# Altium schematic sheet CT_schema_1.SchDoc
size 446 x 435 mm
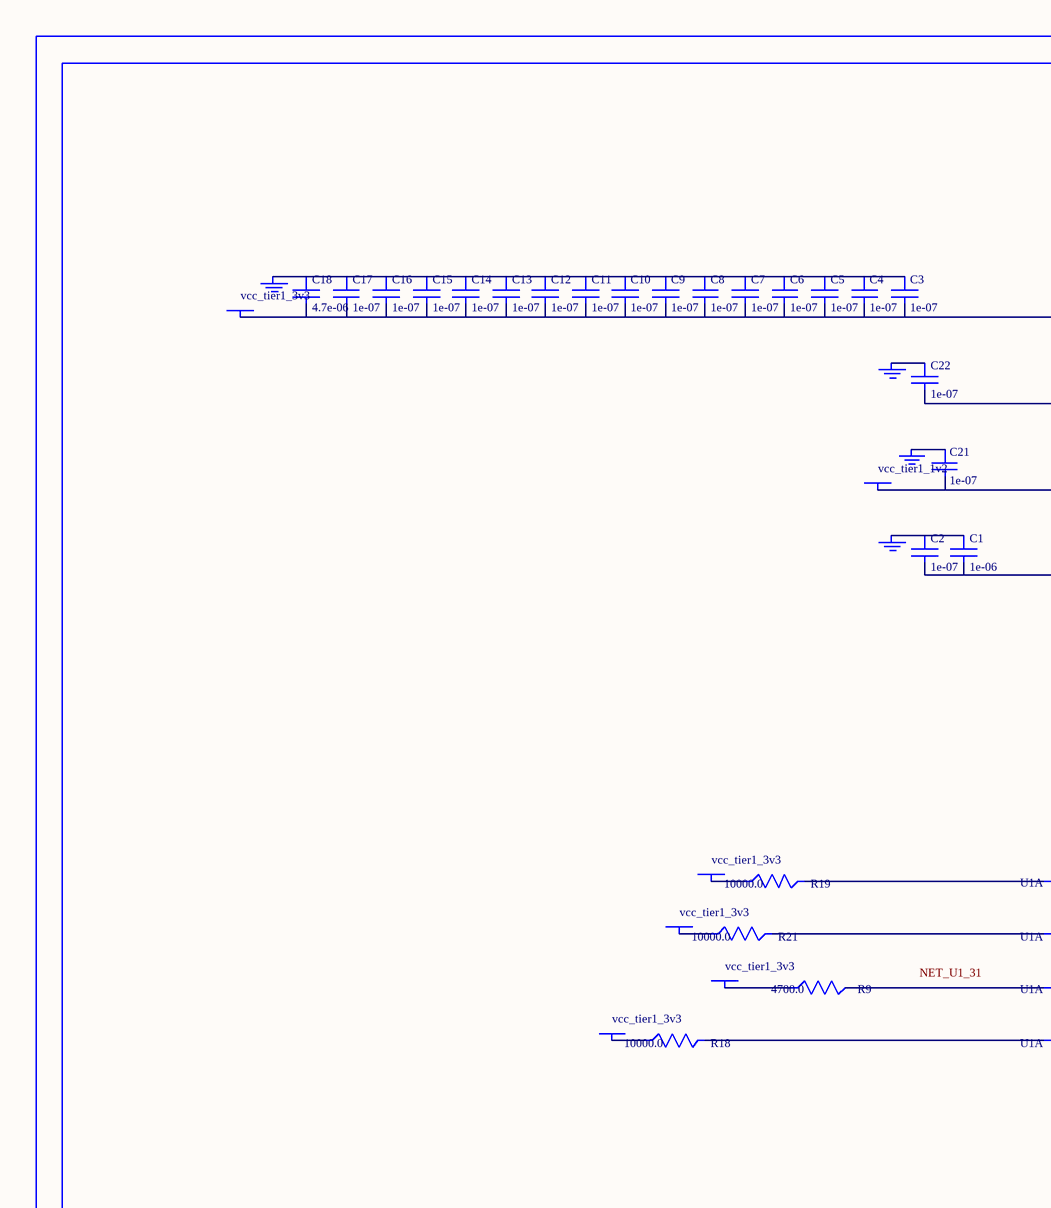
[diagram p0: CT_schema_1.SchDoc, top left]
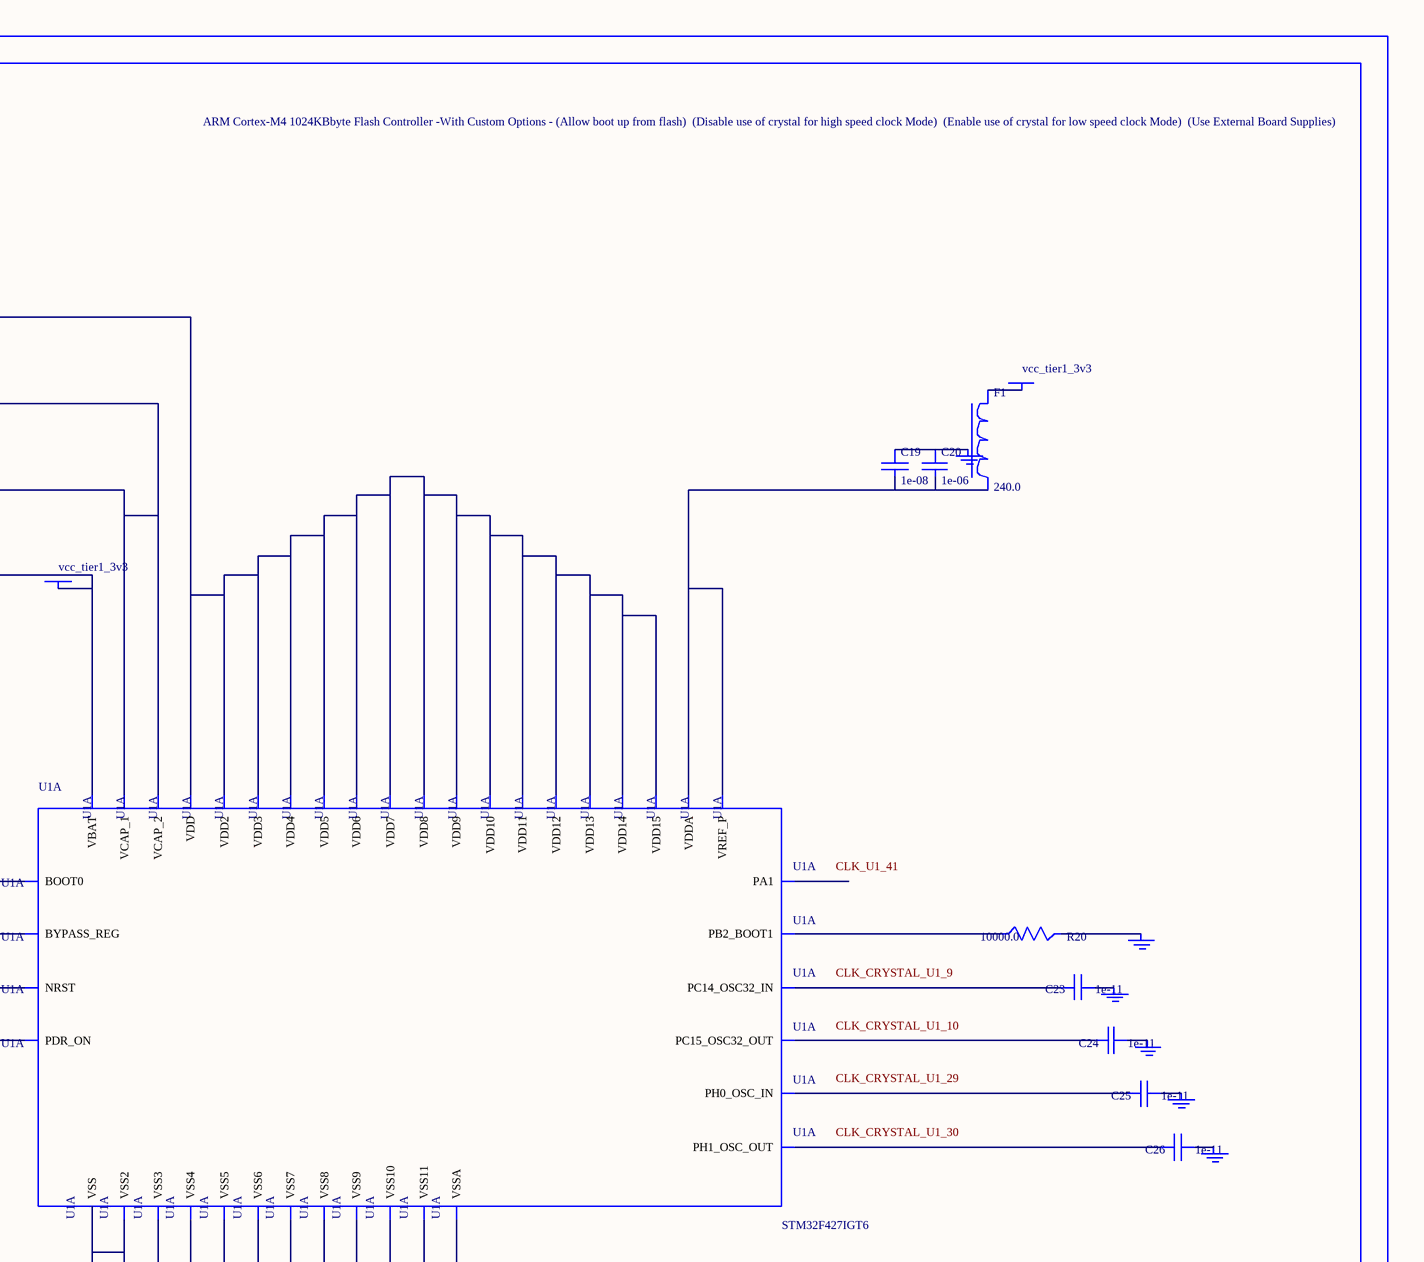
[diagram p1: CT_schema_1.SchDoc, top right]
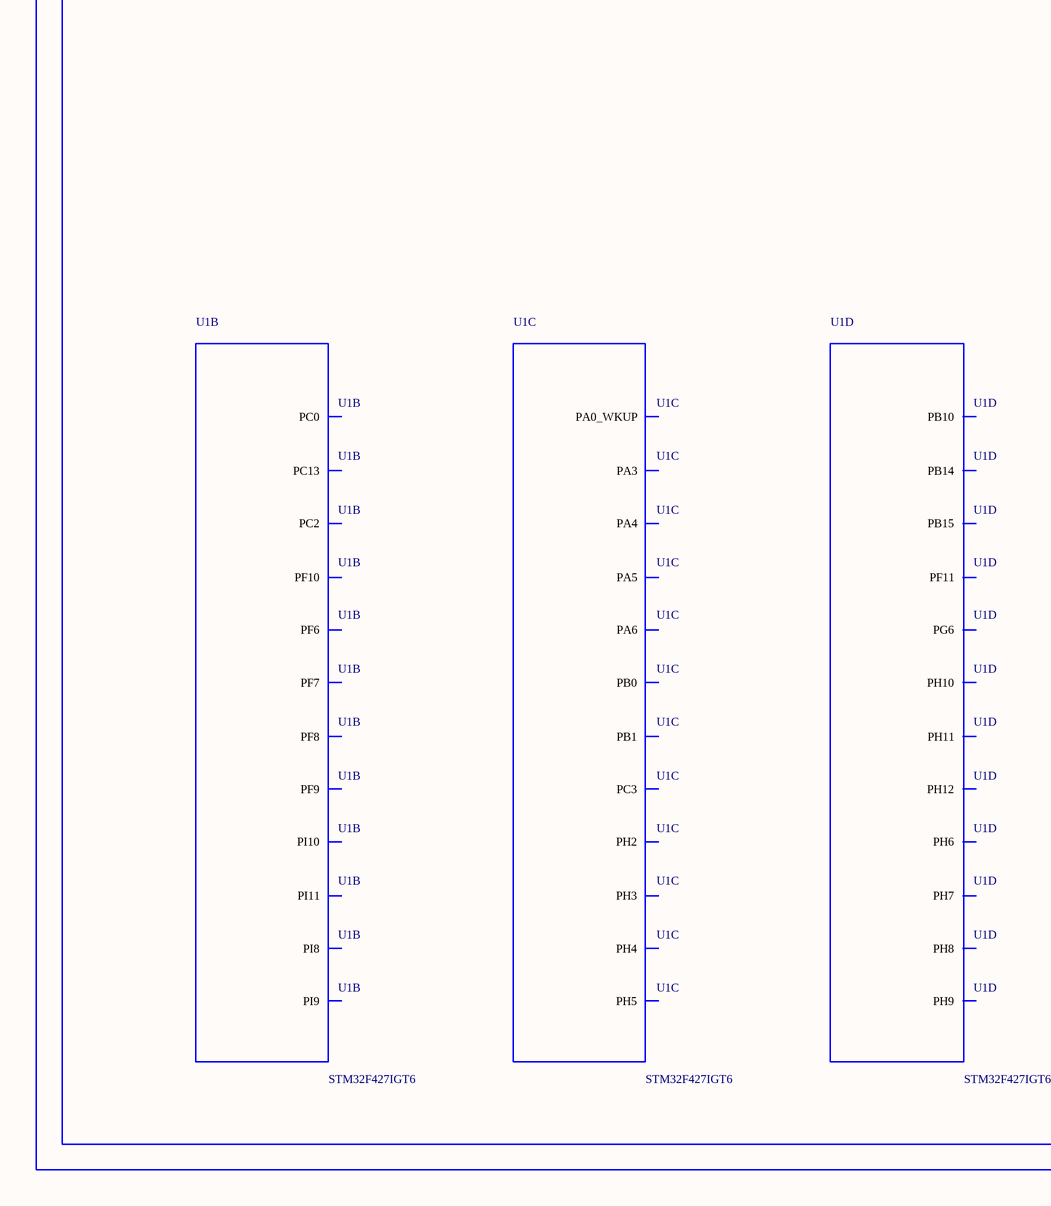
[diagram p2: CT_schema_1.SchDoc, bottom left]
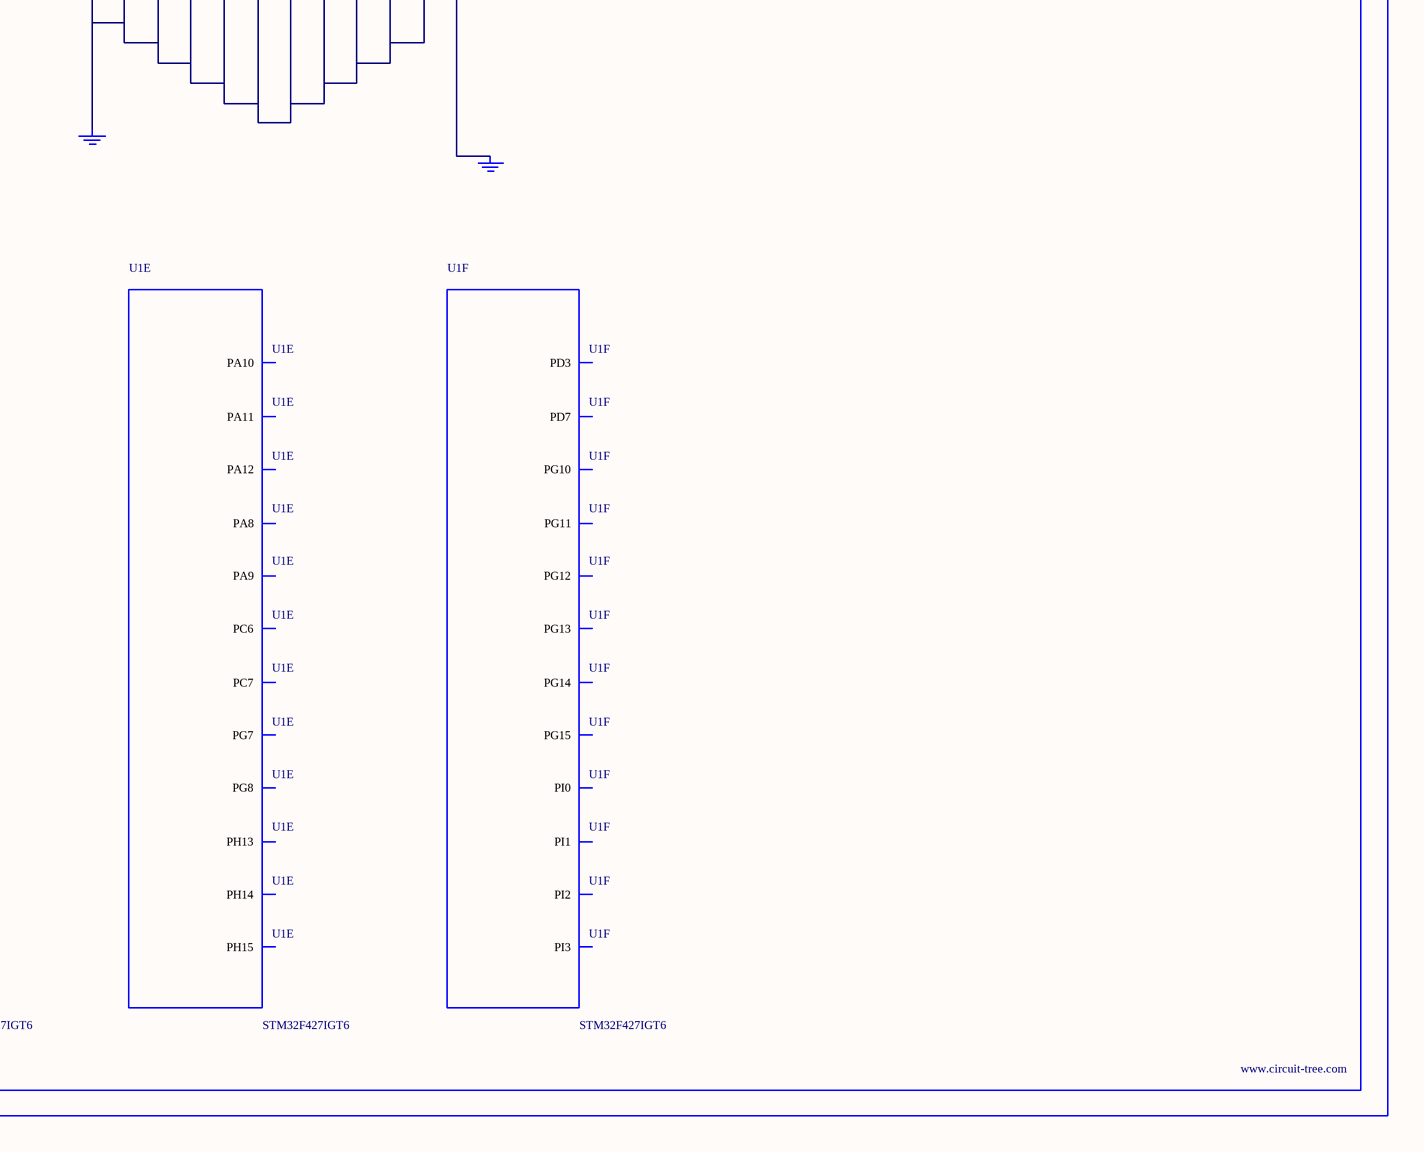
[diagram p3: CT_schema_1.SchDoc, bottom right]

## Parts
BORDER0  (no value)
C1  1e-06  [C0603]
C2  1e-07  [C0603]
C3  1e-07  [C0603]
C4  1e-07  [C0603]
C5  1e-07  [C0603]
C6  1e-07  [C0603]
C7  1e-07  [C0603]
C8  1e-07  [C0603]
C9  1e-07  [C0603]
C10  1e-07  [C0603]
C11  1e-07  [C0603]
C12  1e-07  [C0603]
C13  1e-07  [C0603]
C14  1e-07  [C0603]
C15  1e-07  [C0603]
C16  1e-07  [C0603]
C17  1e-07  [C0603]
C18  4.7e-06  [C0603]
C19  1e-08  [C0603]
C20  1e-06  [C0603]
C21  1e-07  [C0402]
C22  1e-07  [C0402]
C23  1e-11  [C0402]
C24  1e-11  [C0402]
C25  1e-11  [C0402]
C26  1e-11  [C0402]
F1  240.0  [L0603]
GND_INSTANCE_0_0  (no value)
GND_INSTANCE_0_1  (no value)
GND_INSTANCE_0_2  (no value)
GND_INSTANCE_0_3  (no value)
GND_INSTANCE_0_4  (no value)
GND_INSTANCE_0_5  (no value)
GND_INSTANCE_0_6  (no value)
GND_INSTANCE_0_7  (no value)
GND_INSTANCE_0_8  (no value)
GND_INSTANCE_0_9  (no value)
GND_INSTANCE_0_10  (no value)
GND_INSTANCE_0_11  (no value)
POWER_INSTANCE_0_0  vcc_tier1_3v3
POWER_INSTANCE_0_1  vcc_tier1_3v3
POWER_INSTANCE_0_2  vcc_tier1_3v3
POWER_INSTANCE_0_3  vcc_tier1_3v3
POWER_INSTANCE_0_4  vcc_tier1_1v2
POWER_INSTANCE_0_5  vcc_tier1_3v3
POWER_INSTANCE_0_6  vcc_tier1_3v3
POWER_INSTANCE_0_7  vcc_tier1_3v3
R9  4700.0  [R0603]
R18  10000.0  [R0603]
R19  10000.0  [R0603]
R20  10000.0  [R0603]
R21  10000.0  [R0603]
U1  STM32F427IGT6  [LQFP176]  (parts A,B,C,D,E,F of 14)

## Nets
NetC1_1: C1.1 C2.1 GND_INSTANCE_0_0.0(GND)
NetC1_2: C1.2 C2.2 POWER_INSTANCE_0_0.0(PWR) U1.6(VBAT)
NetC3_1: C3.1 C4.1 C5.1 C6.1 C7.1 C8.1 C9.1 C10.1 C11.1 C12.1 C13.1 C14.1 C15.1 C16.1 C17.1 C18.1 GND_INSTANCE_0_3.0(GND)
NetC3_2: C3.2 C4.2 C5.2 C6.2 C7.2 C8.2 C9.2 C10.2 C11.2 C12.2 C13.2 C14.2 C15.2 C16.2 C17.2 C18.2 POWER_INSTANCE_0_1.0(PWR) U1.15(VDD) U1.23(VDD2) U1.36(VDD3) U1.49(VDD4) U1.62(VDD5) U1.72(VDD6) U1.82(VDD7) U1.91(VDD8) U1.103(VDD9) U1.114(VDD10) U1.127(VDD11) U1.136(VDD12) U1.149(VDD13) U1.159(VDD14) U1.172(VDD15)
NetC19_1: C19.1 C20.1 GND_INSTANCE_0_7.0(GND)
NetC19_2: C19.2 C20.2 F1.2 U1.38(VREF_P) U1.39(VDDA)
NetC21_1: C21.1 GND_INSTANCE_0_9.0(GND)
NetC21_2: C21.2 C22.2 POWER_INSTANCE_0_4.0(PWR) U1.81(VCAP_1) U1.125(VCAP_2)
NetC22_1: C22.1 GND_INSTANCE_0_10.0(GND)
NetC23_1: C23.1 GND_INSTANCE_0_1.0(GND)
NetC23_2: C23.2 U1.9(PC14_OSC32_IN)
NetC24_1: C24.1 GND_INSTANCE_0_2.0(GND)
NetC24_2: C24.2 U1.10(PC15_OSC32_OUT)
NetC25_1: C25.1 GND_INSTANCE_0_4.0(GND)
NetC25_2: C25.2 U1.29(PH0_OSC_IN)
NetC26_1: C26.1 GND_INSTANCE_0_5.0(GND)
NetC26_2: C26.2 U1.30(PH1_OSC_OUT)
NetF1_1: F1.1 POWER_INSTANCE_0_2.0(PWR)
NetGND_INSTANCE_0_6_0: GND_INSTANCE_0_6.0(GND) U1.37(VSSA)
NetGND_INSTANCE_0_8_0: GND_INSTANCE_0_8.0(GND) R20.2
NetGND_INSTANCE_0_11_0: GND_INSTANCE_0_11.0(GND) U1.14(VSS) U1.22(VSS2) U1.61(VSS3) U1.71(VSS4) U1.90(VSS5) U1.102(VSS6) U1.113(VSS7) U1.126(VSS8) U1.135(VSS9) U1.148(VSS10) U1.158(VSS11)
NetPOWER_INSTANCE_0_3_0: POWER_INSTANCE_0_3.0(PWR) R21.1
NetPOWER_INSTANCE_0_5_0: POWER_INSTANCE_0_5.0(PWR) R19.1
NetPOWER_INSTANCE_0_6_0: POWER_INSTANCE_0_6.0(PWR) R18.1
NetPOWER_INSTANCE_0_7_0: POWER_INSTANCE_0_7.0(PWR) R9.1
NetR9_2: R9.2 U1.31(NRST)
NetR18_2: R18.2 U1.171(PDR_ON)
NetR19_2: R19.2 U1.166(BOOT0)
NetR20_1: R20.1 U1.58(PB2_BOOT1)
NetR21_2: R21.2 U1.48(BYPASS_REG)

Not connected (* = marked no-connect by the designer): U1 7(PI8) 8(PC13) 11(PI9) 12(PI10) 13(PI11) 24(PF6) 25(PF7) 26(PF8) 27(PF9) 28(PF10) 32(PC0) 34(PC2) 35(PC3) 40(PA0_WKUP) 41(PA1) 43(PH2) 44(PH3) 45(PH4) 46(PH5) 47(PA3) 50(PA4) 51(PA5) 52(PA6) 56(PB0) 57(PB1) 59(PF11) 79(PB10) 83(PH6) 84(PH7) 85(PH8) 86(PH9) 87(PH10) 88(PH11) 89(PH12) 94(PB14) 95(PB15) 110(PG6) 111(PG7) 112(PG8) 115(PC6) 116(PC7) 119(PA8) 120(PA9) 121(PA10) 122(PA11) 123(PA12) 128(PH13) 129(PH14) 130(PH15) 131(PI0) 132(PI1) 133(PI2) 134(PI3) 145(PD3) 151(PD7) 153(PG10) 154(PG11) 155(PG12) 156(PG13) 157(PG14) 160(PG15)

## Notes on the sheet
- Labels drawn without touching a wire or pin: CLK_CRYSTAL_U1_9, CLK_CRYSTAL_U1_10, CLK_CRYSTAL_U1_29, CLK_CRYSTAL_U1_30, CLK_U1_41, NET_U1_31

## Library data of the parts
BORDER0 = BORDER_PAGE0
C1 C20 = C0603C105K3RACTU
C2-C17 = 06035C104K4Z2A
C18 = GRM188R6YA475KE15D
C19 = 06035C103K4Z2A
C21 C22 = C0402C104K3RACTU
C23-C26 = C0402C100K3GACTU
F1 = Z0603C241ASMST
GND_INSTANCE_0_0-GND_INSTANCE_0_11 = GND
POWER_INSTANCE_0_0-POWER_INSTANCE_0_7 = PWR
R9 = RC0603JR-074K7L
R18-R21 = RC0603JR-0710KL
